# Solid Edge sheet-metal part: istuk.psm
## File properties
Author: Argu
Template: Iso Sheet Metal.psm
Last saved by: Argu
Revision: 7
Application: Solid Edge
Accuracy: 0,990
Material Thickness: 0,10 mm
Bend Radius: 1,00 mm
Relief Width: 1,00 mm
Relief Length: 0,00 mm
Neutral Factor: 0,330
Minimum Arc Length: 0,10 mm
Deviational Tolerance: 0,10 mm
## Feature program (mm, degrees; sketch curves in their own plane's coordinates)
base tab "unnamed BaseTab 1"
flange "Flange_1"
flange "Flange_2"
jog tab "JogTab_1"  OffsetDistance = 25 mm
drawn cutout "DrawnCutout_3"
louver "Louver_4"  LouverDepth = 2.5 mm; LouverHeight = 2 mm
bead "unnamed Bead 1"
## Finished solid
Body 1: solid body, 122 faces, 278 edges, 165 vertices.
  Faces by surface: plane 51, cylinder 29, torus 18, cone 16, sphere 4, spline 4
  Edges by curve: line 150, circle 118, curve on surface 8, intersection 2
Bounding box of the edges (mm; curved faces can reach further): 43.735 x 29.999 x 39.023, from (-18.6054, -14.9996, 2.4208) to (25.1301, 14.9996, 41.4439).
Cylindrical faces by radius (mm): R0.1 x16, R1 x4, R1.1 x4, R2.4625 x1, R2.5625 x1, R5.2029 x1, R5.3029 x1, R10 x1
Conical faces (half-angle, radius in mm at the cone's reference point): 15 deg R0.0301 x4, 15 deg R0.0636 x4, 15 deg R0.1267 x4, 15 deg R0.1602 x4
Toroidal faces (ring radius, tube radius in mm): R0.05 r0.1 x8, R0.1602 r0.1 x8, R6.3029 r1 x1, R6.3029 r1.1 x1
Spherical faces by radius (mm): R2.4625 x2, R2.5625 x2
Planar faces by outward normal: oblique 51
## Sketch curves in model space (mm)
line (-3.8816, 9.4883, 10.957) -> (-3.8367, -9.1519, 10.8337)
line (-5.5351, -8.568, 15.5) -> (-5.577, 8.8343, 15.615)
line (-7.2451, 8.1907, 20.1982) -> (-7.2335, -7.984, 20.1663)
line (-8.9046, -7.4095, 24.7575) -> (-8.9405, 7.5366, 24.8563)
circle centre (-12.0932, 0, 33.2258) radius 5.2029
line (0, -14.9996, 0) -> (-12.1383, -9.8983, 33.3498)
arc centre (-11.6517, 0, 32.0128) radius 10 from (-12.1383, -9.8983, 33.3498) through (-15.0719, 0, 41.4097) to (-12.1383, 9.8983, 33.3498)
line (0, 14.9996, 0) -> (-12.1383, 9.8983, 33.3498)
line (-0.0361, 0, 0.0991) -> (0, 14.9996, 0)
line (-0.0361, 0, 0.0991) -> (0, -14.9996, 0)
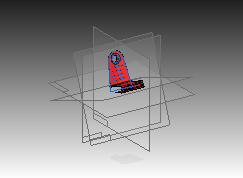
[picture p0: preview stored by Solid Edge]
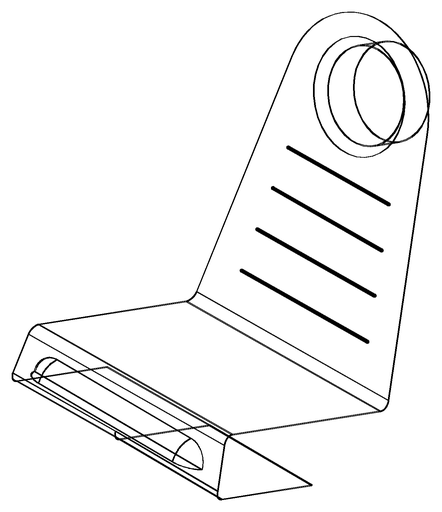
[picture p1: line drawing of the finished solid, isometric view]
